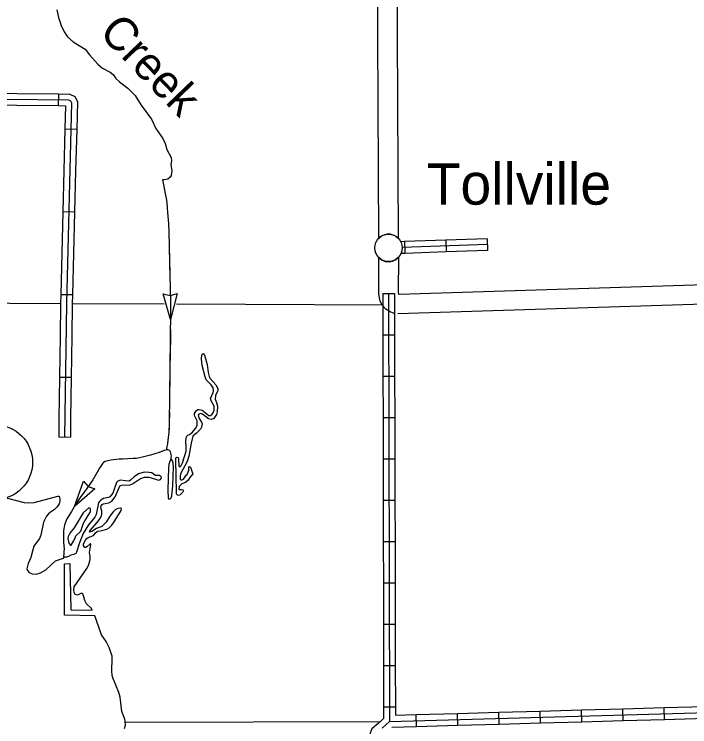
# Model space of a CAD drawing. Extents: x 982240 to 1103002, y 974866 to 1054902.
# Drawn here: x 1028568 to 1037189, y 1002381 to 1011477 of the extents above; entities that cross this region are included whole.
import ezdxf

# ---------------------------------------------------------------- set-up
doc = ezdxf.new("R2010")
doc.units = 0
for name, color, linetype in [('10', 7, 'Continuous'), ('24', 7, 'Continuous'), ('32', 7, 'Continuous'), ('35', 7, 'Continuous'), ('43', 7, 'Continuous'), ('45', 7, 'Continuous'), ('5', 7, 'Continuous'), ('9', 7, 'Continuous'), ('R_Draft', 7, 'Continuous')]:
    doc.layers.add(name, color=color, linetype=linetype)

msp = doc.modelspace()

# ---------------------------------------------------------------- linework, layer by layer
at = {"layer": '10'}
for points in [[(1033174, 1013186.8), (1033237.1, 1013178), (1033309.4, 1013152.7), (1033362, 1013116.5), (1033422.4, 1013046.1), (1033448.6, 1012961.8), (1033469.5, 1008616.7)], [(1033219.5, 1008615.5), (1033198.8, 1012922.8), (1033194.3, 1012928.1), (1033177.8, 1012933.8), (1033139.3, 1012939.2)], [(1033469.5, 1008616.7), (1033461.7, 1008623.5), (1033449.9, 1008633.5), (1033431.7, 1008644.7), (1033417.4, 1008653.5), (1033392.4, 1008662.3), (1033368.6, 1008667.3), (1033345.5, 1008669.1), (1033328, 1008667.9), (1033298, 1008662.3), (1033271.1, 1008652.2), (1033253, 1008642.2), (1033235.5, 1008631), (1033219.5, 1008615.5)], [(1033416.2, 1007658.3), (1033367.8, 1007675.9), (1033308.3, 1007712.5), (1033266.7, 1007756.7), (1033236.6, 1007814.1), (1033219.5, 1007901.5), (1033220, 1008371.3)], [(1033220, 1008371.3), (1033231.8, 1008359.7), (1033246.8, 1008348.4), (1033264.9, 1008337.2), (1033283.6, 1008329.7), (1033301.8, 1008322.2), (1033321.1, 1008320.3), (1033338.6, 1008318.4), (1033356.1, 1008317.2), (1033374.9, 1008320.9), (1033395.5, 1008324.7), (1033413, 1008331.6), (1033431.1, 1008340.3), (1033452.4, 1008354.1), (1033461.1, 1008362.8), (1033470, 1008371)], [(1033470, 1008371), (1033469.5, 1007925.7), (1033473.7, 1007904.3), (1033475.3, 1007903), (1033477.8, 1007902)], [(1033478.7, 1007901.5), (1038595.8, 1008065.3), (1038684.7, 1008056.1), (1038781.1, 1008003.8), (1038834.1, 1007935.6), (1038870.8, 1007824.6), (1038897.6, 1002603.5)], [(1038647.6, 1002602.2), (1038621, 1007783.7), (1038611.9, 1007811.2), (1038609.3, 1007812.6), (1038587.1, 1007814.8), (1033462.9, 1007650.9)]]:
    msp.add_lwpolyline(points, dxfattribs=at)
at = {"layer": '24'}
msp.add_circle((1033345.1, 1008493.7), 175, dxfattribs=at)
at = {"layer": '32'}
for p, q in [((1033548.6, 1008574.2), (1033501.3, 1008572.6)), ((1033548.6, 1008574.2), (1033553.6, 1008424.3)), ((1034076.3, 1008592), (1034081.3, 1008442.1)), ((1034604, 1008609.8), (1034609, 1008459.9)), ((1034606.5, 1008536.2), (1033520, 1008499.6)), ((1033553.6, 1008424.3), (1033505.1, 1008422.6)), ((1033270.9, 1007913.5), (1033420.9, 1007913.8)), ((1033272, 1007385.5), (1033422, 1007385.8)), ((1033273.1, 1006857.5), (1033423.1, 1006857.8)), ((1033274.3, 1006329.5), (1033424.3, 1006329.8)), ((1033275.4, 1005801.5), (1033425.4, 1005801.8)), ((1033276.6, 1005273.5), (1033426.6, 1005273.8)), ((1033277.7, 1004745.5), (1033427.7, 1004745.8)), ((1033278.8, 1004217.5), (1033428.8, 1004217.8)), ((1033280, 1003689.5), (1033430, 1003689.8)), ((1033281.1, 1003161.5), (1033431.1, 1003161.8)), ((1033282.2, 1002633.5), (1033432.2, 1002633.8)), ((1033282.2, 1002633.5), (1033282.6, 1002484.7)), ((1035284.9, 1002430.2), (1035280.7, 1002580.1)), ((1035812.7, 1002445.2), (1035808.5, 1002595.1)), ((1036340.5, 1002460.1), (1036336.3, 1002610.1)), ((1036868.3, 1002475.1), (1036864, 1002625.1)), ((1033701.6, 1002385.2), (1033697.3, 1002535.1)), ((1034229.4, 1002400.2), (1034225.1, 1002550.1)), ((1034757.2, 1002415.2), (1034752.9, 1002565.1)), ((1033386.2, 1002376.3), (1033701.6, 1002385.2))]:
    msp.add_line(p, q, dxfattribs=at)
for points in [[(1034076.3, 1008592), (1033548.6, 1008574.2)], [(1034604, 1008609.8), (1034076.3, 1008592)], [(1034081.3, 1008442.1), (1033553.6, 1008424.3)], [(1034609, 1008459.9), (1034081.3, 1008442.1)], [(1033270.9, 1007913.5), (1033272, 1007385.5)], [(1033344.5, 1007913.6), (1033356.3, 1002449), (1038772.6, 1002602.8)], [(1033420.9, 1007913.8), (1033422, 1007385.8)], [(1033272, 1007385.5), (1033273.1, 1006857.5)], [(1033422, 1007385.8), (1033423.1, 1006857.8)], [(1033273.1, 1006857.5), (1033274.3, 1006329.5)], [(1033423.1, 1006857.8), (1033424.3, 1006329.8)], [(1033274.3, 1006329.5), (1033275.4, 1005801.5)], [(1033424.3, 1006329.8), (1033425.4, 1005801.8)], [(1033275.4, 1005801.5), (1033276.6, 1005273.5)], [(1033425.4, 1005801.8), (1033426.6, 1005273.8)], [(1033276.6, 1005273.5), (1033277.7, 1004745.5)], [(1033426.6, 1005273.8), (1033427.7, 1004745.8)], [(1033277.7, 1004745.5), (1033278.8, 1004217.5)], [(1033427.7, 1004745.8), (1033428.8, 1004217.8)], [(1033278.8, 1004217.5), (1033280, 1003689.5)], [(1033428.8, 1004217.8), (1033430, 1003689.8)], [(1033280, 1003689.5), (1033281.1, 1003161.5)], [(1033430, 1003689.8), (1033431.1, 1003161.8)], [(1033281.1, 1003161.5), (1033282.2, 1002633.5)], [(1033431.1, 1003161.8), (1033432.2, 1002633.8)], [(1033432.2, 1002633.8), (1033432.5, 1002527.6), (1033697.3, 1002535.1)], [(1034752.9, 1002565.1), (1035280.7, 1002580.1)], [(1035280.7, 1002580.1), (1035808.5, 1002595.1)], [(1035808.5, 1002595.1), (1036336.3, 1002610.1)], [(1036336.3, 1002610.1), (1036864, 1002625.1)], [(1036864, 1002625.1), (1037391.8, 1002640.1)], [(1033282.6, 1002484.7), (1033214.1, 1002420.4), (1033130.8, 1002354), (1033108.9, 1002299.9), (1033083.1, 1002004.4)], [(1033697.3, 1002535.1), (1034225.1, 1002550.1)], [(1034225.1, 1002550.1), (1034752.9, 1002565.1)], [(1036868.3, 1002475.1), (1037396.1, 1002490.1)], [(1033356.3, 1002449), (1033264.1, 1002362.6)], [(1033701.6, 1002385.2), (1034229.4, 1002400.2)], [(1034229.4, 1002400.2), (1034757.2, 1002415.2)], [(1034757.2, 1002415.2), (1035284.9, 1002430.2)], [(1035284.9, 1002430.2), (1035812.7, 1002445.2)], [(1035812.7, 1002445.2), (1036340.5, 1002460.1)], [(1036340.5, 1002460.1), (1036868.3, 1002475.1)]]:
    msp.add_lwpolyline(points, dxfattribs=at)
at = {"layer": '35'}
for points in [[(1029112.4, 1011534.5), (1029130.8, 1011434.6), (1029166.2, 1011333), (1029203.1, 1011250.6), (1029245.6, 1011190.4), (1029320.2, 1011125.9), (1029473.7, 1011029.2), (1029529.4, 1010958.2), (1029636.4, 1010839.3), (1029694.6, 1010790.5), (1029794.1, 1010735.6), (1029828.7, 1010708.3), (1029866, 1010656), (1029909.1, 1010612.9), (1030016.2, 1010531.1), (1030060.1, 1010492), (1030110.4, 1010440), (1030188.4, 1010316.4), (1030318.7, 1010138.8), (1030374.6, 1010017.7), (1030463.8, 1009889.3), (1030493.2, 1009828.8), (1030515, 1009751)], [(1030515, 1009751), (1030570.5, 1009645.9), (1030574.5, 1009605.9), (1030565.6, 1009557.5), (1030579.4, 1009478.6), (1030571.7, 1009420.2), (1030558.3, 1009394.8), (1030528.8, 1009373), (1030482.9, 1009363.9), (1030459.9, 1009361.4)], [(1030628.3, 1005748.8), (1030631.9, 1005812.1), (1030643.6, 1005823.5), (1030658.8, 1005819.8), (1030664.2, 1005801.9), (1030667.3, 1005711.6), (1030677.6, 1005698.8), (1030693.4, 1005707.2), (1030714.4, 1005750.9), (1030742.6, 1005832.8), (1030760.1, 1005900.4), (1030763.6, 1005964.7), (1030759.4, 1006016.8), (1030761.1, 1006074.1), (1030769.7, 1006092.3), (1030782.4, 1006104.7), (1030805.3, 1006113.2), (1030842.7, 1006143.2), (1030880.7, 1006187.2), (1030901.8, 1006227.9), (1030904, 1006263), (1030900.4, 1006288), (1030868.9, 1006353.5), (1030867.3, 1006378.6), (1030894.4, 1006417.4), (1030909.2, 1006430.7), (1030928.2, 1006432.2), (1030965.5, 1006421), (1031053.1, 1006355.8), (1031073.2, 1006354.3), (1031093.9, 1006369.8), (1031110.3, 1006395.3), (1031118.7, 1006423.6), (1031118.6, 1006471.8), (1031079.9, 1006541.1), (1031072.2, 1006571), (1031107.6, 1006646.1), (1031112, 1006669.3), (1031106.1, 1006708.3), (1031080.2, 1006747.8), (1031018.6, 1006809.6), (1031004.8, 1006846.4), (1030967.3, 1006994), (1030957.5, 1007073.1), (1030963.2, 1007127.4), (1030977.9, 1007143.8), (1030994.3, 1007126.1), (1031030.1, 1007005.5), (1031042.5, 1006904.5), (1031055.7, 1006851.6), (1031067.3, 1006827.8), (1031140.3, 1006746.2), (1031165.5, 1006698.6), (1031166, 1006674.6), (1031134.5, 1006607.6), (1031132.5, 1006564.4), (1031149.5, 1006520.7)], [(1031149.5, 1006520.7), (1031161.7, 1006471.8), (1031159.3, 1006401.5), (1031151.1, 1006365.2), (1031116.2, 1006316.2), (1031084.4, 1006303.4), (1031047.2, 1006310.5), (1030971.6, 1006371), (1030944.4, 1006379.4), (1030921.6, 1006369.8), (1030914.8, 1006358.6), (1030929.8, 1006316.8), (1030959, 1006269.3), (1030964.4, 1006249.4), (1030958.4, 1006205.1), (1030945, 1006180.7), (1030893, 1006130.3), (1030848.9, 1006089.2), (1030825.9, 1005999.3), (1030795.7, 1005835), (1030773.2, 1005765.3), (1030690.6, 1005610.8), (1030683.4, 1005574.5), (1030684.2, 1005541.4), (1030696.5, 1005529.7), (1030727.3, 1005541.4), (1030763.2, 1005592.4), (1030775, 1005600.7), (1030794.8, 1005656.4), (1030797.8, 1005698.6), (1030805.7, 1005701.8), (1030818.9, 1005695.1), (1030838.4, 1005632.3), (1030845.9, 1005609.4), (1030807, 1005561.4), (1030789.7, 1005528.8), (1030753.3, 1005498.9), (1030708.7, 1005480.8), (1030673.4, 1005446.8), (1030669.3, 1005407.6), (1030704.3, 1005410.4), (1030722.4, 1005406.9), (1030726.7, 1005394.9), (1030717.2, 1005370.6), (1030683.9, 1005339.7), (1030664, 1005333.2), (1030649.8, 1005337.9), (1030638.5, 1005351.7), (1030636.5, 1005610.6), (1030628.3, 1005748.8)], [(1030564.3, 1005787.5), (1030555.6, 1005773.2), (1030541.7, 1005726.7), (1030536.6, 1005685.5), (1030530.1, 1005404.4), (1030531.5, 1005298), (1030540.8, 1005286.2), (1030557.8, 1005288.6), (1030569.5, 1005302.9), (1030579.9, 1005329.3), (1030593.9, 1005461), (1030598.4, 1005699), (1030589.8, 1005770), (1030579.4, 1005786.8)], [(1030579.4, 1005786.8), (1030564.3, 1005787.5)], [(1029539.7, 1005125.3), (1029541.8, 1005166.5), (1029520.5, 1005175), (1029445.8, 1005112.1), (1029334, 1004921.8), (1029276.5, 1004852.2), (1029257.4, 1004811.6), (1029253, 1004785.5), (1029265.5, 1004722.5), (1029287, 1004701), (1029296, 1004700.2), (1029324, 1004749), (1029340.3, 1004780.5), (1029354.4, 1004818.9), (1029419.2, 1004878.6), (1029450.9, 1004977.7), (1029468.2, 1005010.2)], [(1029468.2, 1005010.2), (1029539.7, 1005125.3)]]:
    msp.add_lwpolyline(points, dxfattribs=at)
at = {"layer": '43'}
for p, q in [((1030470.6, 1007909.4), (1030559.1, 1007886.5)), ((1030562.3, 1007578.7), (1030470.6, 1007909.4)), ((1030560.3, 1007886.6), (1030648.3, 1007911)), ((1030648.3, 1007911), (1030562.3, 1007578.7)), ((1029336.3, 1005193.4), (1029450.1, 1005517.2)), ((1029450.1, 1005517.2), (1029509.6, 1005447.9)), ((1029596.7, 1005416.9), (1029336.3, 1005193.4)), ((1029510.6, 1005447.2), (1029596.7, 1005416.9))]:
    msp.add_line(p, q, dxfattribs=at)
for points in [[(1030459.9, 1009361.4), (1030509, 1009101.6), (1030516.8, 1009063.7), (1030521.2, 1009003.6), (1030524.6, 1008945.5), (1030535.8, 1008805.2), (1030539.3, 1008697.9), (1030564.2, 1007792.4), (1030563.5, 1007691), (1030546.7, 1006249.7), (1030542.1, 1006143.2), (1030536, 1006102.9), (1030528.5, 1006039.5), (1030522.5, 1005992.2), (1030517.3, 1005959), (1030512.8, 1005936.8), (1030505.3, 1005913.5)], [(1030459.9, 1009361.4), (1030496.6, 1009166.8)], [(1030518.8, 1009036.9), (1030521.2, 1009003.6), (1030524.6, 1008945.5), (1030535.8, 1008805.2), (1030539.3, 1008697.9), (1030540.9, 1008641.6)], [(1030544.5, 1008509.6), (1030555.4, 1008113.8)], [(1030559, 1007981.8), (1030564.2, 1007792.4), (1030563.5, 1007691), (1030562.3, 1007585.9)], [(1030560.7, 1007453.9), (1030556.1, 1007057.9)], [(1030554.6, 1006926), (1030549.9, 1006530)], [(1030548.4, 1006398), (1030546.7, 1006249.7), (1030544.5, 1006200)], [(1030544.5, 1006200), (1030542.1, 1006143.2), (1030536, 1006102.9), (1030528.5, 1006039.5), (1030523.9, 1006003.3)], [(1030493.4, 1005911.3), (1030417.9, 1005882.4), (1030305.5, 1005846.7), (1030202.9, 1005821.2), (1030127.1, 1005807.4), (1029905.9, 1005796.2), (1029802, 1005783.7), (1029763.2, 1005773.8), (1029730.3, 1005765), (1029705.5, 1005754.3), (1029699.7, 1005747.2), (1029680.2, 1005721.6), (1029657.1, 1005684), (1029572.4, 1005533.5), (1029495.8, 1005422.3), (1029410.3, 1005307.9), (1029350.3, 1005216.2), (1029297.1, 1005130.7), (1029236.4, 1005027.9), (1029209, 1004955), (1029196.6, 1004885.5), (1029198.1, 1004733), (1029203, 1004652.8), (1029201.9, 1004611.7), (1029195.7, 1004533.2)], [(1030467.2, 1005901.3), (1030417.9, 1005882.4), (1030305.5, 1005846.7), (1030202.9, 1005821.2), (1030127.1, 1005807.4), (1030084.7, 1005805.2)], [(1030564.3, 1005787.5), (1030575.1, 1005839.9), (1030564, 1005888.8), (1030558.7, 1005900.7), (1030549.5, 1005908.6), (1030539.4, 1005912.3), (1030527.3, 1005915.1), (1030518.3, 1005916.9), (1030505.3, 1005913.5)], [(1030564.3, 1005787.5), (1030575.1, 1005839.9), (1030564, 1005888.8), (1030558.7, 1005900.7), (1030549.5, 1005908.6), (1030539.4, 1005912.3), (1030527.3, 1005915.1), (1030518.3, 1005916.9), (1030505.3, 1005913.5)], [(1029952.9, 1005798.5), (1029905.9, 1005796.2), (1029802, 1005783.7), (1029763.2, 1005773.8), (1029730.3, 1005765), (1029705.5, 1005754.3), (1029699.7, 1005747.2), (1029680.2, 1005721.6), (1029657.1, 1005684), (1029628.8, 1005633.7)], [(1029562.7, 1005519.5), (1029495.8, 1005422.3), (1029410.3, 1005307.9), (1029350.3, 1005216.2), (1029336.8, 1005194.5)], [(1029268.2, 1005081.7), (1029236.4, 1005027.9), (1029209, 1004955), (1029196.6, 1004885.5), (1029198.1, 1004733), (1029200.1, 1004700.5)], [(1029198.5, 1004568.8), (1029195.7, 1004533.2)]]:
    msp.add_lwpolyline(points, dxfattribs=at)
at = {"layer": '45'}
for p, q in [((1029131.8, 1010459.8), (1029130.4, 1010309.8)), ((1029364.9, 1010004.2), (1029215, 1010008.1)), ((1029337.7, 1008948.6), (1029187.7, 1008952.4)), ((1029310.4, 1007892.9), (1029160.5, 1007896.8)), ((1029295, 1006838), (1029145, 1006840)), ((1029284.8, 1006075.5), (1029134.8, 1006077.5))]:
    msp.add_line(p, q, dxfattribs=at)
for points in [[(1028075.1, 1010396), (1029260.2, 1010384.9), (1029287.5, 1010371.5), (1029300.1, 1010345.7), (1029234, 1007783.4), (1029211.2, 1006076.9)], [(1028075.8, 1010469.6), (1028603.8, 1010464.7)], [(1028603.8, 1010464.7), (1029131.8, 1010459.8)], [(1029131.8, 1010459.8), (1029277.5, 1010458.4), (1029342.6, 1010426.5), (1029374.2, 1010361.9), (1029364.9, 1010004.2)], [(1028074.4, 1010319.6), (1028602.4, 1010314.7)], [(1028602.4, 1010314.7), (1029130.4, 1010309.8)], [(1029130.4, 1010309.8), (1029222.8, 1010308.9), (1029215, 1010008.1)], [(1029215, 1010008.1), (1029201.4, 1009480.3)], [(1029364.9, 1010004.2), (1029351.3, 1009476.4)], [(1029201.4, 1009480.3), (1029187.7, 1008952.4)], [(1029351.3, 1009476.4), (1029337.7, 1008948.6)], [(1029187.7, 1008952.4), (1029174.1, 1008424.6)], [(1029337.7, 1008948.6), (1029324.1, 1008420.8)], [(1029174.1, 1008424.6), (1029160.5, 1007896.8)], [(1029324.1, 1008420.8), (1029310.4, 1007892.9)], [(1029160.5, 1007896.8), (1029157.6, 1007784.9), (1029152, 1007367.9)], [(1029310.4, 1007892.9), (1029307.6, 1007781.9), (1029302, 1007365.9)], [(1029152, 1007367.9), (1029145, 1006840)], [(1029302, 1007365.9), (1029295, 1006838)], [(1029145, 1006840), (1029137.9, 1006312)], [(1029295, 1006838), (1029287.9, 1006310)], [(1029137.9, 1006312), (1029134.8, 1006078)], [(1029287.9, 1006310), (1029284.8, 1006076)]]:
    msp.add_lwpolyline(points, dxfattribs=at)
at = {"layer": '5'}
for points in [[(1018616.9, 1007729), (1022575.1, 1007772.1), (1027854.3, 1007791.2), (1029160.4, 1007783.8)], [(1029321.4, 1007783), (1030480.3, 1007778.8)], [(1030638, 1007778.2), (1033274.3, 1007768.4)], [(1029990.5, 1002437.4), (1033247.5, 1002448.7)]]:
    msp.add_lwpolyline(points, dxfattribs=at)
at = {"layer": '9'}
for points in [[(1029684.7, 1005134.7), (1029672.7, 1005178.6), (1029676.2, 1005202.8), (1029687.9, 1005217.1), (1029704.7, 1005225.5), (1029776.5, 1005240.2), (1029813, 1005262.2), (1029854.9, 1005315.3), (1029910, 1005445), (1029923.7, 1005461.4), (1029960.6, 1005467.3), (1030034.8, 1005465), (1030077.5, 1005482.1), (1030177.1, 1005549.6), (1030228.7, 1005568.9), (1030286.9, 1005567.3), (1030345.4, 1005551.6), (1030395.9, 1005531.7), (1030410, 1005529), (1030435.8, 1005538.6), (1030442.6, 1005548.8), (1030446.2, 1005568), (1030425.6, 1005589.6), (1030376.6, 1005587.4), (1030362.5, 1005592.1), (1030322.7, 1005621.3), (1030289.5, 1005627.5), (1030227.4, 1005629.1), (1030151.7, 1005610.2), (1030098.4, 1005572.9), (1030053.4, 1005527.7), (1030036.6, 1005517.2), (1029988.5, 1005518.1), (1029922.1, 1005528.6), (1029888.3, 1005516.8), (1029872.7, 1005499.4), (1029824.7, 1005364.8), (1029789.7, 1005316.8), (1029768.9, 1005307.3), (1029706.1, 1005292.8), (1029673.5, 1005272.9), (1029654.9, 1005255.4), (1029645.3, 1005239.2), (1029614.6, 1005089.9), (1029597.4, 1005055.4), (1029516.5, 1004959.2), (1029448.9, 1004847.2), (1029402.5, 1004729.7), (1029362.2, 1004609.4), (1029352.6, 1004593.1), (1029329.9, 1004578.5), (1029290, 1004570.6), (1029259.3, 1004553.8), (1029233.5, 1004546.2), (1029208.4, 1004547.6), (1029195.7, 1004533.2)], [(1028004.4, 1005395.4), (1028002.2, 1005376.8), (1028000.8, 1005308.6), (1028017.3, 1005285.9), (1028038.6, 1005274.3), (1028068.8, 1005269), (1028160.4, 1005293.2), (1028188.6, 1005288.9), (1028203.9, 1005276.2), (1028268.8, 1005198.4), (1028289.1, 1005188.9), (1028312.1, 1005190.4), (1028335.8, 1005204), (1028397.4, 1005270.7), (1028418.1, 1005284.2), (1028482.7, 1005298.6), (1028693.8, 1005244.6)], [(1028693.8, 1005244.6), (1028747.2, 1005241.3), (1028820.3, 1005243), (1029124.2, 1005324.9)], [(1029124.2, 1005324.9), (1029137.2, 1005324.2), (1029143.4, 1005315.3), (1029148.3, 1005275.3), (1029147.9, 1005264.2)], [(1029147.9, 1005264.2), (1029140.6, 1005228.4), (1029117.5, 1005187.7), (1029082.2, 1005155.7), (1029027, 1005116.3)], [(1029027, 1005116.3), (1029004.3, 1005100.7), (1028979, 1005068), (1028942.7, 1004991.9), (1028908.4, 1004828.6), (1028889.3, 1004785), (1028819.5, 1004685), (1028802.9, 1004624.4), (1028779.8, 1004539.6), (1028745.5, 1004464.5), (1028730, 1004394.9), (1028735.5, 1004376), (1028757.1, 1004348.4), (1028796.6, 1004332.2), (1028847.7, 1004329.4), (1028903.5, 1004345.8), (1028971.7, 1004385.5), (1029095.3, 1004498.8), (1029195.7, 1004533.2)], [(1029617.8, 1003738.3), (1029597.4, 1003797.1), (1029208.4, 1003807), (1029208.4, 1004461.3), (1029277.5, 1004462.9), (1029288, 1003875.1), (1029563.7, 1003867.5), (1029552.2, 1003889.3), (1029491.7, 1003949.1), (1029470.6, 1003993.8), (1029457.5, 1004040.6), (1029443.7, 1004076.4), (1029427.5, 1004084.1), (1029376.9, 1004059.8), (1029343.6, 1004069.1), (1029332.1, 1004093.9), (1029329.2, 1004130), (1029334.3, 1004168.2), (1029496.3, 1004401.8), (1029515.4, 1004441.4), (1029536.7, 1004517.1), (1029535.9, 1004553.2), (1029527.7, 1004604.2), (1029544.3, 1004707), (1029541.1, 1004717.9), (1029536.1, 1004715.8), (1029495, 1004675.7), (1029483.1, 1004670.4), (1029467, 1004671), (1029452.4, 1004694.8), (1029453.1, 1004711.9), (1029473, 1004759.5), (1029493.4, 1004785.1), (1029511.2, 1004797.5), (1029578.7, 1004823.2), (1029602.1, 1004853.8), (1029631.6, 1004876.6), (1029662.6, 1004880.3), (1029748.2, 1004902.4), (1029779.9, 1004919.2), (1029810.2, 1004949), (1029836.5, 1004983.7), (1029932.1, 1005139.5), (1029935.5, 1005165.7), (1029924.4, 1005170.4), (1029891.4, 1005167.7), (1029855.7, 1005148.8), (1029831.2, 1005125.1), (1029789.5, 1005067.9), (1029743.1, 1004991.6), (1029687.3, 1004936.1), (1029615.8, 1004911.3), (1029557.6, 1004871.8), (1029528.6, 1004866.2), (1029531.3, 1004883.3), (1029625, 1004986.8), (1029662, 1005036.9), (1029681.1, 1005073.4), (1029685.6, 1005097.6), (1029684.7, 1005134.7)], [(1029973.1, 1002359.9), (1029986.2, 1002402.3), (1029985.1, 1002450.5), (1029978.4, 1002479.4), (1029943.1, 1002574.9), (1029917.8, 1002760), (1029904.4, 1002819.9), (1029827, 1003006.7), (1029817.3, 1003036.6), (1029812.9, 1003095.7), (1029818.3, 1003253.3), (1029815.6, 1003281.4), (1029779, 1003393.9), (1029740.2, 1003469.3), (1029680.1, 1003556.2), (1029617.8, 1003738.3)]]:
    msp.add_lwpolyline(points, dxfattribs=at)
at = {"layer": 'R_Draft'}
msp.add_circle((1028325, 1005758), 476.6, dxfattribs=at)

# ---------------------------------------------------------------- texts
at = {"layer": '24'}
msp.add_text('Tollville', height=528, dxfattribs=at).set_placement((1033831.4, 1009046.3))
at = {"layer": '35'}
msp.add_text('Creek', height=422.4, rotation=313.89154, dxfattribs=at).set_placement((1029635.1, 1011231.5))

doc.saveas('drawing.dxf')
